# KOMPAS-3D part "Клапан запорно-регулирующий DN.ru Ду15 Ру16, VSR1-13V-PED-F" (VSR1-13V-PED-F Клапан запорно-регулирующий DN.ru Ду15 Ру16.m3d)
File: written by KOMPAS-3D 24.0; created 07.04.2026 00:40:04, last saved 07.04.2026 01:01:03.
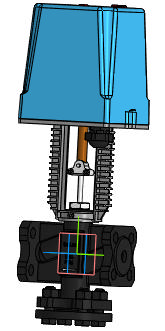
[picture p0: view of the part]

Document properties: Автор: R2D2; Полное имя файла: VSR1-13V-PED-F Клапан запорно-регулирующий DN.ru Ду15 Ру16.cdw

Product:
- Part/product: Клапан запорно-регулирующий DN.ru Ду15 Ру16  | designation VSR1-13V-PED-F
    Масса: 6.1
    Раздел спецификации: Прочие изделия
    Форматы листов документа: A3
    Примечание: D090-02881

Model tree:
1. Операция без истории:1  (labels: SHAPEOBJECT3D_ATTR_BUTT)

Expressions: VSR1-13V-PED-F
